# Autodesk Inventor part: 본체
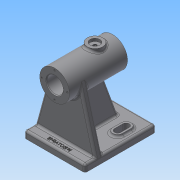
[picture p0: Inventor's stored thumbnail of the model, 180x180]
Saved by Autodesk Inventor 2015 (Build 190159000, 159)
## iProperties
Created: 2019-10
Part Number: 본체
Material: 일반
Document SubType Name: Modeling
Designer: user
Density: 1 g/cm^3
Appearance: 기본값
Author: user
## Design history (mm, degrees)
sketch "스케치1"
  geometry: C1 r 21 at (0, 0); 1 further point
  constraints: 1 centre point, 1 coincident
  dimensions: "d0" = 42 diameter of C1
extrude "돌출1" new body sketch "스케치1" stored distance "d1" = 82; taper "d2" = 0 deg
hole "구멍1" diameter "d5" = 23; stored, may be unused: countersink angle "d9" = 90 deg, drill point angle "d11" = 0 deg; dims "d3" = 10, "d4" = 10, "d6" = 6, "d7" = 4, "d8" = 2, "d10" = 20
hole "구멍2" diameter "d14" = 29; stored, may be unused: countersink angle "d18" = 90 deg, drill point angle "d20" = 0 deg; dims "d12" = 10, "d13" = 10, "d15" = 6, "d16" = 4, "d17" = 2, "d19" = 62
chamfer "모따기1" distance "d21" = 1; stored, may be unused: second distance "d22" = 2, angle "d23" = 45 deg
node "작업 평면1"
node "작업 평면2"
node "작업축1"
sketch "스케치2"
  geometry: C1 r 11 at (0, -16); 2 further points
  constraints: 1 centre point, 1 coincident
  dimensions: "d26" = 22 diameter of C1
extrude "돌출2" join sketch "스케치2" stored distance "d27" = 82; taper "d28" = 0 deg
hole "구멍3" diameter "d31" = 4.917; stored, may be unused: countersink angle "d35" = 90 deg, drill point angle "d37" = 0 deg; dims "d29" = 10, "d30" = 10, "d32" = 12, "d33" = 14, "d34" = 4, "d36" = 20.6
fillet "모깎기1" dims "d38" = 3
sketch "스케치3"
  geometry: C1 r 21 at (0, 0) reference; 1 further point
  constraints: 1 vertical alignment
  dimensions: "d39" = 18 distance of point (0, 18) C1.centre
hole "구멍4" sketch "스케치3" at (0, 18) diameter "d40" = 2.459; stored, may be unused: countersink angle "d44" = 90 deg, drill point angle "d46" = 118 deg; dims "d41" = 8, "d42" = 14, "d43" = 4, "d45" = 10
node "작업축2"
  node "작업 평면3"
  node "작업 평면4"
sketch "스케치4"
  geometry: L1 (29.4, 41)-(-29.4, 41) reference; L2 (-43, -59)-(43, -59); L3 (43, -59)-(43, 41); L4 (43, 41)-(-43, 41); L5 (-43, 41)-(-43, -59); L6 (-43, -59)-(43, 41); L7 (43, -59)-(-43, 41); 3 further points
  constraints: 12 end point, 3 midpoint, 2 parallel, 1 horizontal, 1 perpendicular, 1 point on line, 1 vertical alignment
  dimensions: "d52" = 100 distance of L2.end L3.end; "d53" = 86 distance of L2.start L2.end
extrude "돌출3" join sketch "스케치4" distance "d54" = 10; taper "d55" = 0 deg
node "작업 평면5"
fillet "모깎기2" dims "d57" = 3
fillet "모깎기3" dims "d58" = 3
sketch "스케치7"
  geometry: L1 (-27, 21)-(-27, 33); L2 (-20, 21)-(-20, 33); L3 (-34, 33)-(-34, 21); L4 (40, 59)-(-40, 59) reference; A1 r 7 centre (-27, 21) between (-34, 21) and (-20, 21); A2 r 7 centre (-27, 33) between (-20, 33) and (-34, 33); 2 further points
  constraints: 8 end point, 4 point on circle, 4 tangent, 2 centre point, 1 midpoint, 1 parallel, 1 vertical
  dimensions: "d73" = 14 distance between parallel lines of L3 L2; "d74" = 12 distance of L1.start L1.end; "d76" = 26 distance from line of L1.end L4; "d77" = 27 horizontal distance of point (-27, 27) point (0, 0)
extrude "돌출4" join sketch "스케치7" distance "d78" = 3; taper "d79" = 0 deg
sketch "스케치8"
  geometry: L1 (-27, 21)-(-27, 33); L2 (-22.5, 21)-(-22.5, 33); L3 (-31.5, 33)-(-31.5, 21); L4 (40, 59)-(-40, 59) reference; A1 r 4.5 centre (-27, 21) between (-31.5, 21) and (-22.5, 21); A2 r 4.5 centre (-27, 33) between (-22.5, 33) and (-31.5, 33); 2 further points
  constraints: 8 end point, 4 point on circle, 4 tangent, 2 centre point, 1 midpoint, 1 parallel, 1 vertical
  dimensions: "d80" = 9 distance between parallel lines of L3 L2; "d81" = 12 distance of L1.start L1.end; "d83" = 26 distance from line of L4 L1.end; "d84" = 27 horizontal distance of point (0, 0) point (-27, 27)
extrude "돌출5" cut sketch "스케치8" stored distance "d85" = 3; taper "d86" = 0 deg
node "작업 평면6"
sketch "스케치9"
  geometry: L1 (-40, -76)-(40, -76) reference; L2 (43, -79)-(43, -86) reference; L3 (43, -86)-(-43, -86) reference; L4 (-43, -86)-(-43, -79) reference; L5 (42.896, -78.217)-(20.272, 5.48); L6 (-42.896, -78.217)-(-20.272, 5.48); C1 r 11.5 at (0, 0) reference; A1 r 3 centre (-40, -79) between (-40, -76) and (-43, -79) reference; A2 r 3 centre (40, -79) between (43, -79) and (40, -76) reference; A3 r 21 centre (0, 0) between (20.272, 5.48) and (-20.272, 5.48) reference; 1 further point
  constraints: 4 end point, 4 point on circle, 4 tangent
extrude "돌출6" join sketch "스케치9" distance "d89" = 10; taper "d90" = 0 deg
sketch "스케치10"
  geometry: L1 (20, -18.459)-(20, -23) reference; L2 (20, -23)-(24, -23) reference; L3 (24, -23)-(24, -27) reference; L4 (21, -30)-(21, -41) reference; L5 (21, -41)-(19.23, -41) reference; L6 (19.23, -41)-(19.23, -31) reference; L7 (19.23, -31)-(18, -30.261) reference; L8 (18, -30.261)-(16.77, -31) reference; L9 (16.77, -31)-(16.77, -41) reference; L10 (16.77, -41)-(15.5, -41) reference; L11 (15.5, -41)-(14.5, -40) reference; L12 (14.5, -40)-(14.5, -18.459) reference; L13 (14.5, -18.459)-(20, -18.459) reference; L14 (11.5, 40)-(12.5, 41) reference; L15 (12.5, 41)-(16.77, 41) reference; L16 (16.77, 41)-(16.77, 31) reference; L17 (16.77, 31)-(18, 30.261) reference; L18 (18, 30.261)-(19.23, 31) reference; L19 (19.23, 31)-(19.23, 41) reference; L20 (19.23, 41)-(21, 41) reference; L21 (21, 41)-(21, -2) reference; L22 (24, -5)-(24, -9) reference; L23 (24, -9)-(20, -9) reference; L24 (20, -9)-(20, -13.542) reference; L25 (20, -13.542)-(14.5, -13.542) reference; L26 (14.5, -13.542)-(14.5, 21) reference; L27 (14.5, 21)-(11.5, 21) reference; L28 (11.5, 21)-(11.5, 40) reference; L29 (-79, -59)-(-86, -59) reference; L30 (-86, -59)-(-86, 41) reference; L31 (-86, 41)-(-79, 41) reference; L32 (-76, 38)-(-76, 26) reference; L33 (-76, 26)-(-21, 26) reference; L34 (-21, 26)-(-21, 41) reference; L35 (-21, 41)-(-19.23, 41) reference; L36 (-19.23, 41)-(-19.23, 31) reference; L37 (-19.23, 31)-(-18, 30.261) reference; L38 (-18, 30.261)-(-16.77, 31) reference; L39 (-16.77, 31)-(-16.77, 41) reference; L40 (-16.77, 41)-(-12.5, 41) reference; L41 (-12.5, 41)-(-11.5, 40) reference; L42 (-11.5, 40)-(-11.5, 21) reference; L43 (-11.5, 21)-(-14.5, 21) reference; L44 (-14.5, 21)-(-14.5, -40) reference; L45 (-14.5, -40)-(-15.5, -41) reference; L46 (-15.5, -41)-(-16.77, -41) reference; L47 (-16.77, -41)-(-16.77, -31) reference; L48 (-16.77, -31)-(-18, -30.261) reference; L49 (-18, -30.261)-(-19.23, -31) reference; L50 (-19.23, -31)-(-19.23, -41) reference; L51 (-19.23, -41)-(-21, -41) reference; L52 (-21, -41)-(-21, 16) reference; L53 (-21, 16)-(-76, 16) reference; L54 (-76, 16)-(-76, -56) reference; L55 (-21, -23.982)-(-76, -44); A1 r 3 centre (-79, -56) between (-79, -59) and (-76, -56) reference; A2 r 3 centre (-79, 38) between (-76, 38) and (-79, 41) reference; 1 further point
  constraints: 2 end point, 2 point on line, 2 other
  dimensions: "d91" = 15 distance from line of L29 L55.end; "d92" = 70 deg angle of L54 L55
feature "리브3" sketch "스케치10" dims "d93" = 1, "d94" = 10, "d95" = 0, "d96" = 0, "d97" = 1, "d98" = 1
fillet "모깎기5" dims "d99" = 3
fillet "모깎기6" dims "d100" = 3
fillet "모깎기7" dims "d101" = 3
fillet "모깎기8" dims "d102" = 3
node "작업 평면7"
sketch "스케치11"
  geometry: L1 (-40, -41)-(40, -41) reference; L2 (-43, 56)-(-43, -38) reference; 2 further points
  constraints: 1 other
  dimensions: "d104" = 43 distance from line of point (0, -34) L2; "d105" = 7 distance from line of L1 point (0, -34)
feature "엠보싱1" sketch "스케치11" dims "d0" = 42, "d106" = 0.5, "d107" = 0
node "솔리드1"
pattern_circular "원형 패턴1" dims angle "d48" = 360 deg
mirror "대칭1"
mirror "대칭2"
mirror "대칭3"
node "절단 모서리 투영3"
node "절단 모서리 투영4"
other parameters: "d24" = -25, "d25" = 24, "d50" = 0, "d51" = -86, "d56" = -15, "d88" = -15
